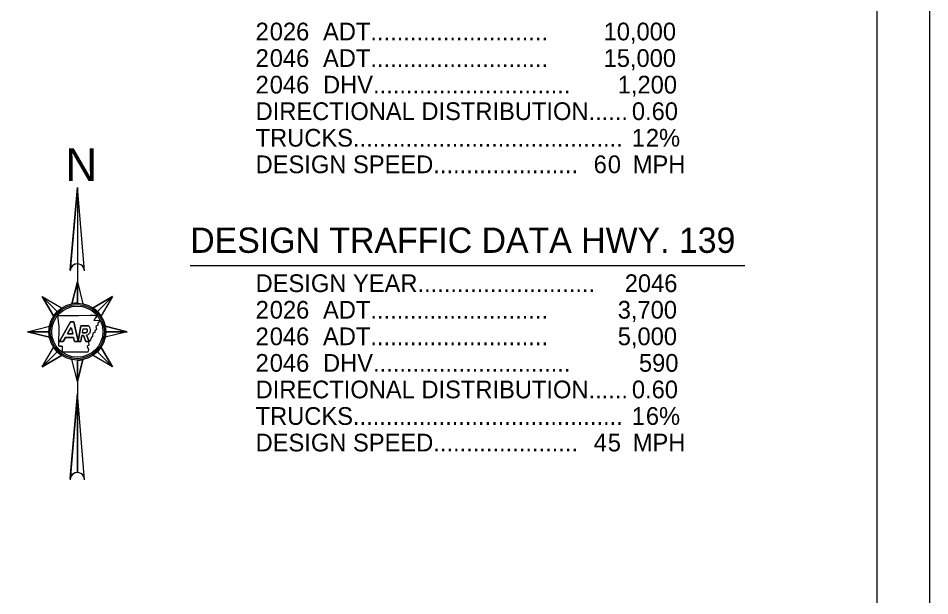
# Model space of a CAD drawing. Extents: x -0.54 to 1.64, y 0 to 0.92.
# Drawn here: x 1.0564 to 1.4167, y 0.2283 to 0.4566 of the extents above; entities that cross this region are included whole.
import ezdxf

# ---------------------------------------------------------------- set-up
doc = ezdxf.new("R2010")
doc.units = 0
for name, color, linetype in [('SHET_Annotations', 7, 'Continuous'), ('SHET_Border-Lines', 7, 'Continuous'), ('SHET_Border-Text', 7, 'Continuous')]:
    doc.layers.add(name, color=color, linetype=linetype)

msp = doc.modelspace()

# ---------------------------------------------------------------- linework, layer by layer
at = {"layer": 'SHET_Annotations'}
for p, q in [((1.079742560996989, 0.38969297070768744), (1.079742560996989, 0.34521548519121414)), ((1.079742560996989, 0.35243505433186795), (1.077548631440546, 0.3437695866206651)), ((1.079742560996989, 0.3439852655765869), (1.079742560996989, 0.35243505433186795)), ((1.065801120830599, 0.34666032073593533), (1.0717760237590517, 0.3406854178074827)), ((1.0717760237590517, 0.3406854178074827), (1.0658011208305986, 0.3466603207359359)), ((1.0658011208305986, 0.3466603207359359), (1.0703771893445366, 0.33898156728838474)), ((1.09368400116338, 0.3466603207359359), (1.0860052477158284, 0.34208425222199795)), ((1.087709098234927, 0.34068541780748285), (1.09368400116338, 0.3466603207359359)), ((1.087709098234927, 0.34068541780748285), (1.09368400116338, 0.3466603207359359)), ((1.0726272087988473, 0.32877217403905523), (1.0770724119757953, 0.33662253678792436)), ((1.0770724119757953, 0.33662253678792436), (1.0783934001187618, 0.33662253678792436)), ((1.0600263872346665, 0.3327188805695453), (1.0684761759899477, 0.3327188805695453)), ((1.0684761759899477, 0.3327188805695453), (1.0600263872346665, 0.3327188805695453)), ((1.0600263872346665, 0.3327188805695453), (1.0686918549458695, 0.33052495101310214)), ((1.0758972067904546, 0.33185352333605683), (1.0773511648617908, 0.3344212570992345)), ((1.0758972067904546, 0.33185352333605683), (1.0779006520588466, 0.33185352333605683)), ((1.081074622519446, 0.3349850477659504), (1.0841615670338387, 0.3349850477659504)), ((1.0817446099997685, 0.3322005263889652), (1.0830685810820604, 0.3322005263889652)), ((1.0820367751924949, 0.33387697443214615), (1.0834863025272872, 0.33387697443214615)), ((1.0994587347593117, 0.3327188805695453), (1.0907932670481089, 0.33491281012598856)), ((1.0910089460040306, 0.3327188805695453), (1.0994587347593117, 0.3327188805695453)), ((1.0910089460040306, 0.3327188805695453), (1.0994587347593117, 0.3327188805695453)), ((1.074152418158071, 0.32877217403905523), (1.0726272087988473, 0.32877217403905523)), ((1.075085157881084, 0.33041942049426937), (1.074152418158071, 0.32877217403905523)), ((1.0782075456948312, 0.33041942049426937), (1.075085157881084, 0.33041942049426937)), ((1.0811471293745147, 0.32877217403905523), (1.0785600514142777, 0.32877217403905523)), ((1.0821171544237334, 0.3312689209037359), (1.081582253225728, 0.3312689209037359)), ((1.083039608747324, 0.32877217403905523), (1.0821171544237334, 0.3312689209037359)), ((1.0843955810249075, 0.32877217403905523), (1.083039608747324, 0.32877217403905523)), ((1.0834239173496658, 0.3314021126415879), (1.0843955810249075, 0.32877217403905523)), ((1.0658011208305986, 0.3187774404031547), (1.071776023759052, 0.3247523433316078)), ((1.071776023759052, 0.3247523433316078), (1.0658011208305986, 0.3187774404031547)), ((1.0877090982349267, 0.32475234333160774), (1.0936840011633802, 0.31877744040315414)), ((1.0877090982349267, 0.32475234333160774), (1.09368400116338, 0.3187774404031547)), ((1.09368400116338, 0.3187774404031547), (1.0891079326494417, 0.3264561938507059)), ((1.0658011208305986, 0.3187774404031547), (1.07347987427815, 0.3233535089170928)), ((1.079741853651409, 0.32145249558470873), (1.079742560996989, 0.32145320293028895)), ((1.079742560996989, 0.31300270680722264), (1.0819364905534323, 0.3216681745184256)), ((1.079742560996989, 0.3214524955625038), (1.079742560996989, 0.2853862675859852)), ((1.079742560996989, 0.3214524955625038), (1.079742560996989, 0.31300270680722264)), ((1.079742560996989, 0.3082933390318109), (1.076964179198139, 0.2746749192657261)), ((1.079742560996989, 0.27702912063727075), (1.079742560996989, 0.3082933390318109))]:
    msp.add_line(p, q, dxfattribs=at)
for points in [[(1.0825591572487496, 0.35673879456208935), (1.079742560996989, 0.3896929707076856), (1.0769259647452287, 0.35673879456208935)], [(1.0769668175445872, 0.3572167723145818), (1.079742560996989, 0.3896929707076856), (1.079742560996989, 0.3595553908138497)], [(1.077548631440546, 0.3437695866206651), (1.079742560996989, 0.35243505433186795), (1.0819364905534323, 0.3437695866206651)], [(1.077548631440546, 0.34376958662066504), (1.079742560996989, 0.35243505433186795), (1.079742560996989, 0.3439852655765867)], [(1.0703771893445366, 0.33898156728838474), (1.0658011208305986, 0.3466603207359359), (1.07347987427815, 0.34208425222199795)], [(1.0703771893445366, 0.3389815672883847), (1.0658011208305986, 0.3466603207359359), (1.0717760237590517, 0.3406854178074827)], [(1.0860052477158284, 0.34208425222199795), (1.09368400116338, 0.3466603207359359), (1.0891079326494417, 0.33898156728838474)], [(1.0860052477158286, 0.34208425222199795), (1.09368400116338, 0.3466603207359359), (1.0877090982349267, 0.3406854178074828)], [(1.0720506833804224, 0.3391682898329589), (1.0764469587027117, 0.33916557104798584), (1.0803049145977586, 0.33917372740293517), (1.0848561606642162, 0.3392444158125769), (1.0869659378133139, 0.33929335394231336)], [(1.0723687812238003, 0.3272736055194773), (1.0726134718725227, 0.3346496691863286), (1.0720506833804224, 0.3391682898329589), (1.0764469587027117, 0.33916557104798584), (1.0803049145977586, 0.33917372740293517), (1.0848561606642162, 0.3392444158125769), (1.0869659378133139, 0.33929335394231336)], [(1.0723687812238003, 0.3272736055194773), (1.0726134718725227, 0.3346496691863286), (1.0720506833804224, 0.3391682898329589)], [(1.0841615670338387, 0.33498504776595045), (1.081074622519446, 0.3349850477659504), (1.0800284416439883, 0.3289820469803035), (1.0783934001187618, 0.33662253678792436), (1.0770724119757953, 0.33662253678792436), (1.0726272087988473, 0.32877217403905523), (1.074152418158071, 0.32877217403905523), (1.075085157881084, 0.33041942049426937), (1.0782075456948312, 0.33041942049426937), (1.0785600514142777, 0.32877217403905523), (1.0811471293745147, 0.32877217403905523), (1.081582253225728, 0.3312689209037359), (1.0821171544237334, 0.3312689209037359), (1.083039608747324, 0.32877217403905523), (1.0842285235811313, 0.32877217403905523), (1.0841717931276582, 0.328720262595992), (1.0842323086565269, 0.3274315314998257), (1.0836901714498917, 0.3268240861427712), (1.0841841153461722, 0.32571821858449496), (1.0838420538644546, 0.3246200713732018), (1.073877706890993, 0.3246363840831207), (1.0738722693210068, 0.32683588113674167)], [(1.0783934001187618, 0.33662253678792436), (1.0800284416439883, 0.3289820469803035), (1.081074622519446, 0.3349850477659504)], [(1.0863433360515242, 0.337259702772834), (1.0863134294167, 0.3371699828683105), (1.088346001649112, 0.33727442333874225), (1.0887276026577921, 0.3368759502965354), (1.0877789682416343, 0.33609641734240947), (1.0878813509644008, 0.3353093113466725), (1.0870681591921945, 0.33477296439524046), (1.0873464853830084, 0.333562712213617), (1.086719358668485, 0.33299062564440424), (1.0866633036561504, 0.3323684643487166), (1.0859008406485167, 0.3320940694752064), (1.085782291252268, 0.33092083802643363), (1.0852344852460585, 0.3303341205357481), (1.0849696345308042, 0.3294503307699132), (1.0843533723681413, 0.3288864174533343), (1.0834239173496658, 0.3314021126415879)], [(1.0883470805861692, 0.33727329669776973), (1.0887276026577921, 0.3368759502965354), (1.0877789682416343, 0.33609641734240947), (1.0878813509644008, 0.3353093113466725), (1.0870681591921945, 0.33477296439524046), (1.0873464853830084, 0.333562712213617), (1.086719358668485, 0.3329906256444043), (1.0866633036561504, 0.3323684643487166), (1.0859008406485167, 0.3320940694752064), (1.085782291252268, 0.33092083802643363), (1.0852344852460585, 0.3303341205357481), (1.0849696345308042, 0.3294503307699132), (1.0841717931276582, 0.328720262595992), (1.0842323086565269, 0.3274315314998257), (1.0836901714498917, 0.3268240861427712), (1.0841841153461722, 0.32571821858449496), (1.0838420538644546, 0.3246200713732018)], [(1.0863134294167, 0.3371699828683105), (1.088376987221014, 0.3372760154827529)], [(1.0686918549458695, 0.33052495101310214), (1.0600263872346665, 0.3327188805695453), (1.0686918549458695, 0.33491281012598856)], [(1.0686918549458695, 0.33052495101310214), (1.0600263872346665, 0.33271888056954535), (1.0684761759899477, 0.33271888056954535)], [(1.0773511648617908, 0.3344212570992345), (1.0779006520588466, 0.33185352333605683)], [(1.0817446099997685, 0.3322005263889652), (1.0820367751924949, 0.33387697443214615)], [(1.0830685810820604, 0.33220052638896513), (1.0817446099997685, 0.3322005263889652), (1.0820367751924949, 0.33387697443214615), (1.083486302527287, 0.33387697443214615)], [(1.0907932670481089, 0.33491281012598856), (1.0994587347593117, 0.3327188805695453), (1.0907932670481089, 0.33052495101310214)], [(1.0907932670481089, 0.33491281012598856), (1.0994587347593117, 0.33271888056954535), (1.0910089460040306, 0.33271888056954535)], [(1.0785600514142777, 0.32877217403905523), (1.0782075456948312, 0.33041942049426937)], [(1.081582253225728, 0.3312689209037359), (1.0811471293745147, 0.32877217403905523)], [(1.07347987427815, 0.3233535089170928), (1.0658011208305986, 0.3187774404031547), (1.0703771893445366, 0.3264561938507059)], [(1.0734798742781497, 0.32335350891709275), (1.0658011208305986, 0.3187774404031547), (1.071776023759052, 0.32475234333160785)], [(1.0838420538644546, 0.3246200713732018), (1.073877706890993, 0.3246363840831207), (1.0738722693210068, 0.32683588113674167)], [(1.0891079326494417, 0.3264561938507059), (1.09368400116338, 0.3187774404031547), (1.0860052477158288, 0.3233535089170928)], [(1.0891079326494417, 0.3264561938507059), (1.09368400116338, 0.3187774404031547), (1.0877090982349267, 0.3247523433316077)], [(1.0819364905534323, 0.3216681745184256), (1.079742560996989, 0.31300270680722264), (1.077548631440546, 0.3216681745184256)], [(1.0819364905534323, 0.3216681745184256), (1.079742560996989, 0.3130027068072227), (1.079742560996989, 0.3214524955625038)], [(1.0825591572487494, 0.27421252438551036), (1.079742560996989, 0.3082933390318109), (1.0769259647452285, 0.27421252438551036)], [(1.076964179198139, 0.2746749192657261), (1.079742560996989, 0.3082933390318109), (1.079742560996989, 0.27702912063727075)]]:
    msp.add_lwpolyline(points, dxfattribs=at)
msp.add_lwpolyline([(1.0779006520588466, 0.33185352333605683), (1.0758972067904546, 0.33185352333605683), (1.0773511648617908, 0.3344212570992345)], close=True, dxfattribs=at)
for radius in [0.0112663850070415, 0.010703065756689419, 0.010139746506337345]:
    msp.add_circle((1.079742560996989, 0.3327188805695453), radius, dxfattribs=at)
for centre, radius, start, end in [((1.079742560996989, 0.35673879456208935), 0.0028165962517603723, 0, 180.00000000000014), ((1.079742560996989, 0.35673879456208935), 0.0028165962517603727, 90, 170.22959486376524), ((1.079742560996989, 0.3327188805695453), 0.011266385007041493, 90.00000000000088, 101.2290882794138), ((1.079742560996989, 0.3327188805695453), 0.011266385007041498, 90.00000000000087, 101.2290882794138), ((1.079742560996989, 0.3327188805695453), 0.011266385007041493, 135.00000000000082, 146.22908827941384), ((1.079742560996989, 0.33271888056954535), 0.0112663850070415, 135.00000000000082, 146.22908827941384), ((1.079742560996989, 0.3327188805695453), 0.011266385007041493, 45.000000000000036, 56.22908827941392), ((1.079742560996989, 0.33271888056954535), 0.0112663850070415, 45.000000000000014, 56.2290882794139), ((1.079742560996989, 0.3327188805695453), 0.011266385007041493, 180, 191.22908827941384), ((1.079742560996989, 0.33271888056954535), 0.0112663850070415, 180, 191.22908827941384), ((1.0827512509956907, 0.3331698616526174), 0.001019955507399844, 288.12683022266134, 43.89015949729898), ((1.0827512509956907, 0.3331698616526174), 0.0010199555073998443, 288.12683022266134, 43.890159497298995), ((1.083013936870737, 0.33335391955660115), 0.0019944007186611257, 281.8626194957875, 54.87052455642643), ((1.083013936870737, 0.33335391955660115), 0.0019944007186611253, 281.86261949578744, 54.8705245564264), ((1.079742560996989, 0.3327188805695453), 0.011266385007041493, 0, 11.229088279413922), ((1.079742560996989, 0.33271888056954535), 0.011266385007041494, 0, 11.229088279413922), ((1.079742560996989, 0.3327188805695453), 0.011266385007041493, 224.99999999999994, 236.2290882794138), ((1.079742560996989, 0.33271888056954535), 0.0112663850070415, 224.99999999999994, 236.2290882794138), ((1.079742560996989, 0.3327188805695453), 0.011266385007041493, 314.99999999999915, 326.2290882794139), ((1.079742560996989, 0.33271888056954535), 0.011266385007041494, 314.99999999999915, 326.2290882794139), ((1.079742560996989, 0.3327188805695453), 0.011266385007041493, 269.99999999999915, 281.2290882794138), ((1.079742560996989, 0.33271888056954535), 0.011266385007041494, 269.9999999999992, 281.2290882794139), ((1.079742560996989, 0.27421252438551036), 0.0028165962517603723, 0, 180.0000000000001), ((1.079742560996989, 0.27421252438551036), 0.0028165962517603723, 89.99999999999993, 170.5510966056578), ((1.079742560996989, 0.27421252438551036), 0.0028165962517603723, 90, 170.5510966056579)]:
    msp.add_arc(centre, radius, start, end, dxfattribs=at)
for points in [[(1.0869659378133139, 0.33929335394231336), (1.0869685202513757, 0.3392532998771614), (1.0869734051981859, 0.33921343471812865), (1.0869795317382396, 0.33917372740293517), (1.08698325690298, 0.33914958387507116), (1.0870093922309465, 0.33913323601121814), (1.0870175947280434, 0.339111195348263), (1.0870304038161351, 0.3390767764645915), (1.0870031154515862, 0.3390307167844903), (1.0870230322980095, 0.33899700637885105), (1.0870347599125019, 0.33897715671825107), (1.0870509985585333, 0.3389618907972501), (1.087069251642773, 0.3389480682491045), (1.0870944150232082, 0.3389290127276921), (1.08712321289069, 0.3389184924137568), (1.0871480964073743, 0.33889913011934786), (1.0871764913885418, 0.3388770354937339), (1.0872007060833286, 0.33885467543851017), (1.0872187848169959, 0.3388202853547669), (1.087234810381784, 0.3387898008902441), (1.0872388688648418, 0.33875837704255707), (1.087235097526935, 0.3387278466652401), (1.0872311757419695, 0.3386960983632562), (1.0872158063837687, 0.3386649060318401), (1.0872133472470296, 0.33863268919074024), (1.0872106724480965, 0.3385976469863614), (1.0872113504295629, 0.338561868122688), (1.0872079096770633, 0.3385266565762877), (1.087204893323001, 0.3384957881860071), (1.0872009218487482, 0.3384650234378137), (1.0871970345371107, 0.338434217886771), (1.087193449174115, 0.3384058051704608), (1.0871924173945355, 0.33837730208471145), (1.087180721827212, 0.33834993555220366), (1.0871678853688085, 0.33831989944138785), (1.0871397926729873, 0.33830217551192), (1.0871154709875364, 0.3382819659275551), (1.0870949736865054, 0.3382649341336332), (1.0870729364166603, 0.3382504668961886), (1.0870529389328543, 0.3382330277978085), (1.0870326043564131, 0.3382152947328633), (1.0870136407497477, 0.33819618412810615), (1.0869958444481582, 0.3381759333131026), (1.0869798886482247, 0.3381577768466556), (1.0869724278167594, 0.3381328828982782), (1.086955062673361, 0.3381161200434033), (1.0869319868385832, 0.33809384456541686), (1.08690755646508, 0.3380730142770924), (1.086884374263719, 0.33805086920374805), (1.086860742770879, 0.33802829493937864), (1.086837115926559, 0.33800571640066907), (1.0868136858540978, 0.33798289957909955), (1.0867939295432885, 0.33796366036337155), (1.086775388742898, 0.33794337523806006), (1.0867565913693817, 0.3379230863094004), (1.0867349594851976, 0.33789973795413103), (1.0867168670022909, 0.3378734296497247), (1.0866994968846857, 0.33784696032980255), (1.0866833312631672, 0.3378223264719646), (1.0866917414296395, 0.3377850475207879), (1.0866723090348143, 0.33776267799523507), (1.0866533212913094, 0.3377408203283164), (1.086629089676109, 0.33772428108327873), (1.0866097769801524, 0.3377028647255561), (1.0865934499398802, 0.3376847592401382), (1.0865771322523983, 0.33766663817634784), (1.0865608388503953, 0.33764848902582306), (1.086538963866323, 0.3376241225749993), (1.0865171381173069, 0.3375997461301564), (1.0864955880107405, 0.33757508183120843), (1.0864779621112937, 0.3375549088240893), (1.0864757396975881, 0.3375247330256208), (1.0864629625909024, 0.3375016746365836), (1.0864462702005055, 0.33747155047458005), (1.0864161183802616, 0.33744833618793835), (1.0864004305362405, 0.3374173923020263), (1.0863880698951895, 0.3373930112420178), (1.0863974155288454, 0.3373607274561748), (1.0863868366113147, 0.3373358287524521), (1.0863769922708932, 0.3373126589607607), (1.0863579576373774, 0.3372927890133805), (1.0863460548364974, 0.3372705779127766), (1.0863443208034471, 0.3372673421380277), (1.0863398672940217, 0.3372620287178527), (1.0863433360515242, 0.337259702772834)], [(1.0738722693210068, 0.32683588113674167), (1.07387602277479, 0.3268343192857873), (1.073881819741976, 0.32683064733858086), (1.0738831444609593, 0.3268304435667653), (1.0738899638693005, 0.3268293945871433), (1.0738500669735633, 0.3268557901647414), (1.0738314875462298, 0.32686578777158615), (1.073808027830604, 0.3268784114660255), (1.0737868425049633, 0.3268957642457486), (1.0737607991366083, 0.326901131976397), (1.0737347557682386, 0.3269064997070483), (1.073708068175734, 0.32690319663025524), (1.0736819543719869, 0.3269065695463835), (1.0736484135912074, 0.3269109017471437), (1.0736148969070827, 0.32691579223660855), (1.0735813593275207, 0.3269201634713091), (1.0735533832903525, 0.3269238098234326), (1.0735226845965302, 0.3269251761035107), (1.0734970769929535, 0.32692831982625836), (1.07346560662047, 0.326932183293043), (1.0734391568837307, 0.32699458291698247), (1.0734100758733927, 0.3269854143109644), (1.0733793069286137, 0.3269757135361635), (1.0733485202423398, 0.32694259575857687), (1.0733176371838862, 0.32692560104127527), (1.0732861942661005, 0.3269082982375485), (1.0732468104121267, 0.32689154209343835), (1.073214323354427, 0.326882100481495), (1.0731919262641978, 0.3268755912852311), (1.0731775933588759, 0.3269305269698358), (1.0731545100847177, 0.32693103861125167), (1.0731290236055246, 0.32693160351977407), (1.0731024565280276, 0.3268989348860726), (1.0730756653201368, 0.3268984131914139), (1.07305784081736, 0.32689806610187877), (1.0730389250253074, 0.3269165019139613), (1.0730212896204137, 0.32691472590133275), (1.0729854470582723, 0.32691111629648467), (1.0729630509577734, 0.32685175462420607), (1.0729261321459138, 0.3268494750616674), (1.072896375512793, 0.32684763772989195), (1.0728662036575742, 0.32687800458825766), (1.07283641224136, 0.3268739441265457), (1.0728146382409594, 0.3268709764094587), (1.0727929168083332, 0.32685867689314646), (1.072771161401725, 0.3268549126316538), (1.0727450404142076, 0.32685039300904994), (1.0727157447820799, 0.3268495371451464), (1.0726895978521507, 0.3268576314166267), (1.0726595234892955, 0.3268669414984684), (1.0727010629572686, 0.326938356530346), (1.0726732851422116, 0.3269500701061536), (1.0726496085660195, 0.3269600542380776), (1.0726187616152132, 0.32695348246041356), (1.0725944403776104, 0.32696366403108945), (1.0725707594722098, 0.3269735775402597), (1.0725402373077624, 0.3269788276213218), (1.0725264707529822, 0.32700172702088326), (1.0725077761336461, 0.32703282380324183), (1.0724949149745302, 0.32706477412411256), (1.0724802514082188, 0.32709688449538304), (1.0724691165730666, 0.3271212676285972), (1.0724589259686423, 0.3271459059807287), (1.072447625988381, 0.32717029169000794), (1.0724293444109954, 0.3272097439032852), (1.0724101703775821, 0.3272435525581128), (1.0723687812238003, 0.3272736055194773)]]:
    msp.add_open_spline(points, degree=3, dxfattribs=at)
for points in [[(1.0869659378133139, 0.33929335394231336), (1.0869795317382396, 0.33917372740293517), (1.0870175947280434, 0.339111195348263), (1.0870230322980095, 0.33899700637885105), (1.087069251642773, 0.3389480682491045), (1.0871480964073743, 0.33889913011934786), (1.0872187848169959, 0.3388202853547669), (1.087235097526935, 0.3387278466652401), (1.0872133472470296, 0.33863268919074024), (1.0872079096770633, 0.3385266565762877), (1.0871970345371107, 0.338434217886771), (1.087180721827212, 0.33834993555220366), (1.0871154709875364, 0.3382819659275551), (1.0870529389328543, 0.33823302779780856), (1.0869958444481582, 0.3381759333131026), (1.086955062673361, 0.3381161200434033), (1.086884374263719, 0.33805086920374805), (1.0868136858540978, 0.33798289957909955), (1.0867565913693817, 0.3379230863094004), (1.0866994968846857, 0.33784696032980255), (1.0866723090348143, 0.33776267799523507), (1.0866097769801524, 0.3377028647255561), (1.0865608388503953, 0.3376484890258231), (1.0864955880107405, 0.33757508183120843), (1.0864629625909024, 0.3375016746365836), (1.0864004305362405, 0.3374173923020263), (1.0863868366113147, 0.3373358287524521), (1.0863460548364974, 0.3372705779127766), (1.0863433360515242, 0.337259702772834)], [(1.0738722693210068, 0.32683588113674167), (1.0738831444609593, 0.3268304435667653), (1.0738314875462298, 0.32686578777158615), (1.0737607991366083, 0.326901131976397), (1.0736819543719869, 0.3269065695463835), (1.0735813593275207, 0.3269201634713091), (1.0734970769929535, 0.32692831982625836), (1.0734100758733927, 0.3269854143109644), (1.0733176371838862, 0.32692560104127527), (1.073214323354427, 0.326882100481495), (1.0731545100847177, 0.32693103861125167), (1.0730756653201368, 0.3268984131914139), (1.0730212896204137, 0.32691472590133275), (1.0729261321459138, 0.3268494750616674), (1.07283641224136, 0.3268739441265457), (1.072771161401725, 0.3268549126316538), (1.0726895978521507, 0.3268576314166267), (1.0726732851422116, 0.3269500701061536), (1.0725944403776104, 0.32696366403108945), (1.0725264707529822, 0.32700172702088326), (1.0724802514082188, 0.32709688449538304), (1.072447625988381, 0.32717029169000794), (1.0723687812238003, 0.3272736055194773)]]:
    msp.add_spline(points, degree=3, dxfattribs=at)
at = {"layer": 'SHET_Border-Lines'}
for points in [[(0, 0), (1.416666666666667, 0), (1.416666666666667, 0.9166666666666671), (0, 0.9166666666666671)], [(0.04166666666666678, 0.02083333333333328), (1.395833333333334, 0.02083333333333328), (1.395833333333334, 0.8958333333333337), (0.04166666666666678, 0.8958333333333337)]]:
    msp.add_lwpolyline(points, close=True, dxfattribs=at)
at = {"layer": 'SHET_Border-Text'}
msp.add_line((1.1243672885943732, 0.3588783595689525), (1.3435292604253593, 0.3588783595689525), dxfattribs=at)

# ---------------------------------------------------------------- texts
at = {"layer": 'SHET_Annotations'}
for s, height, p in [('10,000', 0.006999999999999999, (1.2877472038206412, 0.44787835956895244)), ('15,000', 0.006999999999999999, (1.2877472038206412, 0.4373783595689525)), ('1,200', 0.006999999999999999, (1.2933377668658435, 0.4268783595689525)), ('0.60', 0.006999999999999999, (1.2989283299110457, 0.41637835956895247)), ('1', 0.006999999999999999, (1.2988633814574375, 0.40587835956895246)), ('2%', 0.006999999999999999, (1.3044539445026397, 0.40587835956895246)), ('N', 0.012999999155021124, (1.074992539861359, 0.39225047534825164)), ('6', 0.006999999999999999, (1.2838153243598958, 0.39537835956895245)), ('0 ', 0.006999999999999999, (1.289405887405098, 0.39537835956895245)), ('MPH', 0.006999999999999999, (1.2992780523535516, 0.39537835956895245)), ('2046', 0.006999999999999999, (1.2961005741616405, 0.34837835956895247)), ('3,700', 0.006999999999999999, (1.2933377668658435, 0.33787835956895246)), ('5,000', 0.006999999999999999, (1.2933377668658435, 0.3273783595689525)), ('DWB 7-27-17', 0.00021906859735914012, (1.0790528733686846, 0.32239143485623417)), ('590', 0.006999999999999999, (1.3017211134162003, 0.3168783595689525)), ('0.60', 0.006999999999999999, (1.2989283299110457, 0.3063783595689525)), ('1', 0.006999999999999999, (1.2988633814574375, 0.2958783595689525)), ('6%', 0.006999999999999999, (1.3044539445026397, 0.2958783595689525)), ('4', 0.006999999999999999, (1.2838153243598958, 0.28537835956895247)), ('5 ', 0.006999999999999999, (1.289405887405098, 0.28537835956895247)), ('MPH', 0.006999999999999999, (1.2992780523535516, 0.28537835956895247))]:
    msp.add_text(s, height=height, dxfattribs=at).set_placement(p)
at = {"layer": 'SHET_Border-Text'}
for s, height, p in [('2', 0.006999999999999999, (1.1502031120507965, 0.44787835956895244)), ('026 ', 0.006999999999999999, (1.1557936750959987, 0.44787835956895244)), ('ADT...........................', 0.006999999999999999, (1.1768469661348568, 0.44787835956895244)), ('2', 0.006999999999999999, (1.1502031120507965, 0.4373783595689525)), ('046 ', 0.006999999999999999, (1.1557936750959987, 0.4373783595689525)), ('ADT...........................', 0.006999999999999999, (1.1768469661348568, 0.4373783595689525)), ('2', 0.006999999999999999, (1.1502031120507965, 0.4268783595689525)), ('046 ', 0.006999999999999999, (1.1557936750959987, 0.4268783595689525)), ('DHV..............................', 0.006999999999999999, (1.1768469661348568, 0.4268783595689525)), ('DIRECTIONAL DISTRIBUTION......', 0.006999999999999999, (1.1502031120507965, 0.41637835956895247)), ('TRUCKS.........................................', 0.006999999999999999, (1.1502031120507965, 0.40587835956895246)), ('DESIGN SPEED......................', 0.006999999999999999, (1.1502031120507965, 0.39537835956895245)), ('DESIGN TRAFFIC DATA HWY. 139', 0.01, (1.1243672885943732, 0.3638783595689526)), ('DESIGN YEAR...........................', 0.006999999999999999, (1.1502031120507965, 0.34837835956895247)), ('2', 0.006999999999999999, (1.1502031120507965, 0.33787835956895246)), ('026 ', 0.006999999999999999, (1.1557936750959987, 0.33787835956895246)), ('ADT...........................', 0.006999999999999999, (1.1768469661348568, 0.33787835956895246)), ('2', 0.006999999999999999, (1.1502031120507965, 0.3273783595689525)), ('046 ', 0.006999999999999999, (1.1557936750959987, 0.3273783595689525)), ('ADT...........................', 0.006999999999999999, (1.1768469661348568, 0.3273783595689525)), ('2', 0.006999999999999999, (1.1502031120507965, 0.3168783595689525)), ('046 ', 0.006999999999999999, (1.1557936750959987, 0.3168783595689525)), ('DHV..............................', 0.006999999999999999, (1.1768469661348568, 0.3168783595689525)), ('DIRECTIONAL DISTRIBUTION......', 0.006999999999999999, (1.1502031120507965, 0.3063783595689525)), ('TRUCKS.........................................', 0.006999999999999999, (1.1502031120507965, 0.2958783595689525)), ('DESIGN SPEED......................', 0.006999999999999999, (1.1502031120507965, 0.28537835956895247))]:
    msp.add_text(s, height=height, dxfattribs=at).set_placement(p)

doc.saveas('drawing.dxf')
